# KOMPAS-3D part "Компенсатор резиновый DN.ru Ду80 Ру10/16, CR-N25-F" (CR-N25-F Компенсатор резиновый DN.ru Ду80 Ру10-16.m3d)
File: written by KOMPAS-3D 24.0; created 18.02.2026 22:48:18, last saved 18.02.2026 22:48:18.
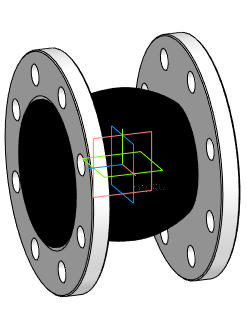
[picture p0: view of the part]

Document properties: Автор: DN.RU; Полное имя файла: D:\PROJECT CAD\DN.RU\...178(1)(ACTUALE). CR-N25-F Компенсатор резиновый DN.ru Ру10-16\DN80\CR-N25-F Компенсатор резиновый DN.ru Ду80 Ру10-16.m3d

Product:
- Body: Твердое тело2  | qty 1
    Масса: 10.337867
- Part/product: Компенсатор резиновый DN.ru Ду80 Ру10/16  | designation CR-N25-F
    Масса: 7.5
    Раздел спецификации: Прочие изделия
    Комментарий: D140-02393
    Примечание: D140-02393
    additional columns: Типовые

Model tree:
1. Твердое тело2  (labels: Твердое тело2)

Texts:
  CR-N25-F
